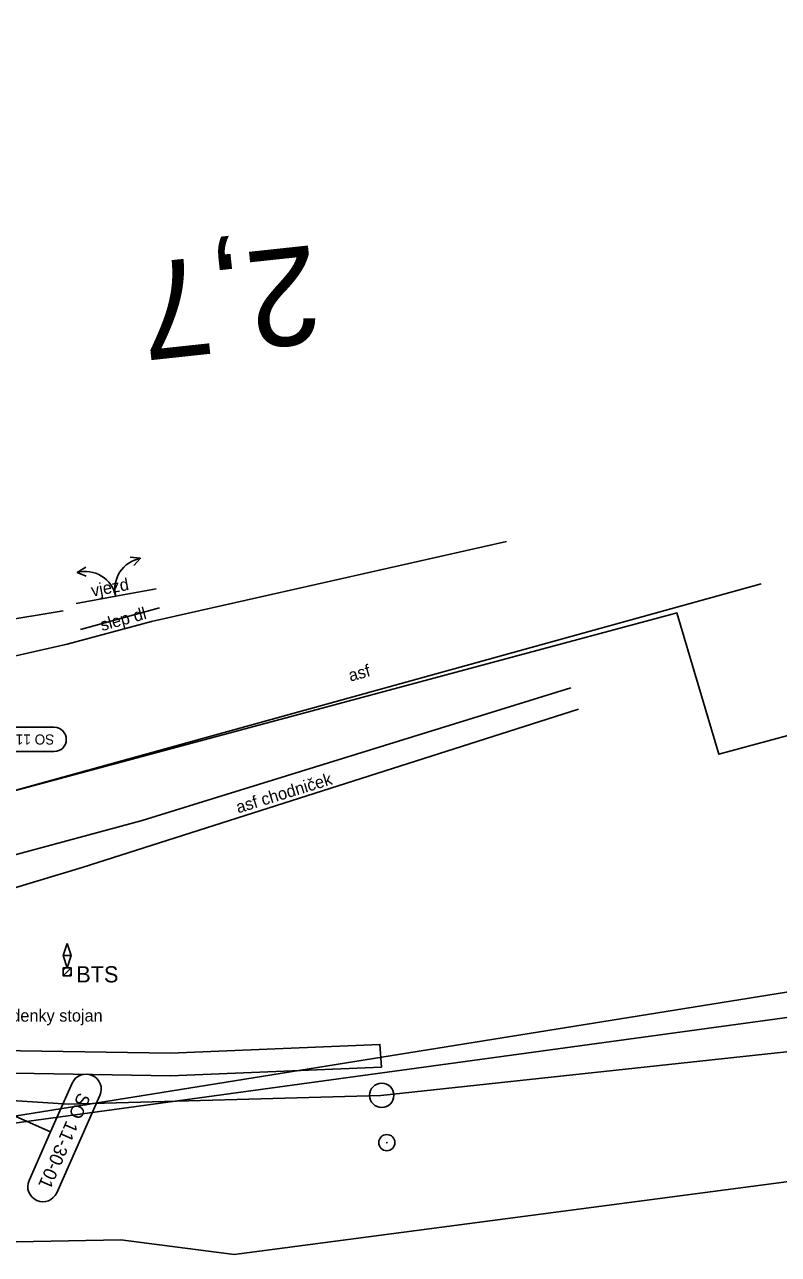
# Model space of a CAD drawing. Extents: x -728800 to -728100, y -1073200 to -1072700.
# Drawn here: x -728483.9 to -728437.4, y -1073054.1 to -1072978.2 of the extents above; entities that cross this region are included whole.
import ezdxf

# ---------------------------------------------------------------- set-up
doc = ezdxf.new("R2010")
doc.units = 0
for name, color, linetype in [('A1_OBVOD Spravy železnic', 7, 'Continuous'), ('B4_Bodové pole', 7, 'Continuous'), ('B6_JŽM', 7, 'Continuous'), ('KTA_členění PS a SO', 7, 'Continuous'), ('ZZZ_popisky', 7, 'Continuous')]:
    doc.layers.add(name, color=color, linetype=linetype)

msp = doc.modelspace()

# ---------------------------------------------------------------- linework, layer by layer
at = {"layer": 'A1_OBVOD Spravy železnic'}
for points in [[(-728503.24, -1073052.34), (-728501.946, -1073043.293), (-728501.19, -1073037.94), (-728499.78, -1073032.61), (-728497.54, -1073030.15), (-728493.68, -1073027.94), (-728443.97, -1073014.59), (-728443.68, -1073014.51), (-728441.09, -1073023.23), (-728428.92, -1073019.94), (-728429.82, -1073016.43), (-728427.49, -1073015.84), (-728421.24, -1073014.23), (-728422.34, -1073010.27), (-728422.77, -1073008.34), (-728418.21, -1073007), (-728380.57, -1072997.2), (-728343.1, -1072987.57), (-728330.49, -1072984.52), (-728326.79, -1072988.95)], [(-728503.24, -1073052.34), (-728496.81, -1073052.21), (-728491.97, -1073053.44), (-728477.97, -1073053.19), (-728470.97, -1073054.08), (-728434.43, -1073049.27), (-728361.73, -1073039.5), (-728349.166, -1073038.984)]]:
    msp.add_lwpolyline(points, dxfattribs=at)
at = {"layer": 'B4_Bodové pole'}
msp.add_line((-728502.086, -1073048.369), (-728399.517, -1073034.362), dxfattribs=at)
msp.add_lwpolyline([(-728665.963, -1072915.444), (-728594.709, -1073015.734), (-728502.086, -1073048.369), (-728347.458, -1073023.537)], dxfattribs=at)
at = {"layer": 'B6_JŽM'}
for p, q in [((-728480.722, -1073013.936), (-728478.281, -1073013.483)), ((-728478.281, -1073013.483), (-728475.783, -1073013.02)), ((-728499.729, -1073017.446), (-728481.523, -1073014.371)), ((-728480.448, -1073015.539), (-728475.586, -1073014.192)), ((-728481.532, -1073035.645), (-728481.032, -1073035.645)), ((-728481.532, -1073036.553), (-728481.374, -1073036.395)), ((-728481.52, -1073036.895), (-728481.032, -1073036.407)), ((-728481.167, -1073036.895), (-728481.032, -1073036.76)), ((-728461.516, -1073047.179), (-728461.616, -1073047.189))]:
    msp.add_line(p, q, dxfattribs=at)
for points in [[(-728300.809, -1073024.355), (-728320.8, -1073026.914), (-728374.008, -1073033.722), (-728429.095, -1073040.747), (-728461.932, -1073044.273), (-728481.199, -1073044.815), (-728499.353, -1073043.648), (-728506.01, -1073042.737), (-728514.574, -1073041.329), (-728535.848, -1073035.998), (-728561.353, -1073026.113), (-728583.963, -1073013.524), (-728603.757, -1072998.891), (-728619.185, -1072984.418), (-728634.193, -1072966.825), (-728646.078, -1072949.194), (-728656.182, -1072930.072), (-728664.987, -1072910.227), (-728668.627, -1072901.808), (-728681.252, -1072876.016), (-728691.886, -1072859.663)], [(-728494.628, -1073019.466), (-728481.269, -1073016.431), (-728476.07, -1073015.036), (-728454.183, -1073010.103)], [(-728477.387, -1073011.078), (-728476.758, -1073011.142), (-728477.169, -1073011.593)], [(-728480.119, -1073011.693), (-728480.66, -1073012.02), (-728480.096, -1073012.252)], [(-728491.401, -1073027.273), (-728490.555, -1073027.131), (-728438.49, -1073012.708)], [(-728491.25, -1073027.888), (-728489.777, -1073030.86), (-728476.655, -1073027.306), (-728450.209, -1073019.139)], [(-728449.745, -1073020.446), (-728480.35, -1073030.208), (-728490.255, -1073033.191), (-728496.482, -1073035.776)], [(-728481.282, -1073034.895), (-728481.532, -1073035.645), (-728481.282, -1073036.395), (-728481.032, -1073035.645), (-728481.282, -1073034.895)], [(-728486.835, -1073041.479), (-728474.913, -1073041.665), (-728461.988, -1073041.13), (-728461.886, -1073042.523), (-728474.902, -1073043.068), (-728486.937, -1073042.858)]]:
    msp.add_lwpolyline(points, dxfattribs=at)
msp.add_lwpolyline([(-728481.532, -1073036.395), (-728481.032, -1073036.395), (-728481.032, -1073036.895), (-728481.532, -1073036.895)], close=True, dxfattribs=at)
for centre, radius in [((-728461.879, -1073044.267), 0.75), ((-728461.566, -1073047.184), 0.5)]:
    msp.add_circle(centre, radius, dxfattribs=at)
for centre, start, end in [((-728476.418, -1073013.028), 100.20503, 193.72491), ((-728480.158, -1073013.871), 11.65548, 105.17536)]:
    msp.add_arc(centre, 1.917, start, end, dxfattribs=at)
at = {"layer": 'KTA_členění PS a SO'}
for points in [[(-728487.074, -1073021.564), (-728482.074, -1073021.564)], [(-728482.074, -1073023.064), (-728487.074, -1073023.064)]]:
    msp.add_lwpolyline(points, dxfattribs=at)
msp.add_arc((-728482.08, -1073022.314), 0.75, 270.45289, 89.54711, dxfattribs=at)
at = {"layer": 'ZZZ_popisky'}
for points in [[(-728495.863, -1073040.505), (-728482.3, -1073046.517), (-728480.971, -1073043.517)], [(-728479.256, -1073044.276), (-728481.915, -1073050.276)], [(-728483.63, -1073049.516), (-728482.3, -1073046.517)]]:
    msp.add_lwpolyline(points, dxfattribs=at)
for centre, start, end in [((-728480.113, -1073043.897), 336.09682, 156.09682), ((-728482.773, -1073049.896), 156.09682, 336.09682)]:
    msp.add_arc(centre, 0.937, start, end, dxfattribs=at)

# ---------------------------------------------------------------- texts
at = {"layer": 'B6_JŽM'}
for s, height, rotation, p in [('2,7', 6, 186.12887, (-728466.031, -1072991.802)), ('vjezd', 0.75, 10.50685, (-728479.728, -1073013.51)), ('slep dl', 0.75, 15.4852, (-728479.123, -1073015.635)), ('asf', 0.75, 15.48375, (-728463.812, -1073018.752)), ('asf chodniček', 0.75, 17.16163, (-728470.731, -1073026.881))]:
    msp.add_text(s, height=height, rotation=rotation, dxfattribs=at).set_placement(p)
for s, height, p in [('BTS', 1, (-728480.716, -1073037.303)), ('jízdenky stojan', 0.75, (-728485.725, -1073039.721))]:
    msp.add_text(s, height=height, dxfattribs=at).set_placement(p)
at = {"layer": 'KTA_členění PS a SO'}
msp.add_text('SO 11-30-01', height=0.625, rotation=180, dxfattribs=at).set_placement((-728482.075, -1073022.005))
at = {"layer": 'ZZZ_popisky'}
msp.add_text('SO 11-30-01', height=0.82031, rotation=246.4372, dxfattribs=at).set_placement((-728480.568, -1073044.044))

doc.saveas('drawing.dxf')
